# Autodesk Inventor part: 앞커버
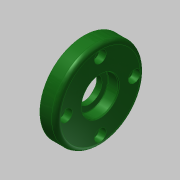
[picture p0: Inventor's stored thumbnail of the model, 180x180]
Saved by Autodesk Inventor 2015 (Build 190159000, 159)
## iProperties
Created: 2015-11
Part Number: 앞커버
Material: 알루미늄 6061
Document SubType Name: Modeling
Designer: mduedu
Density: 1 g/cm^3
Appearance: 매끄러움 - 짙은 산림 녹색
Author: mduedu
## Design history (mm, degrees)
sketch "스케치5"
  geometry: C1 r 30 at (0, 0); 2 further points
  constraints: 2 coincident, 1 centre point
  dimensions: "d66" = 60 diameter of C1
extrude "돌출2" new body sketch "스케치5" distance "d67" = 11; taper "d68" = 0 deg
sketch "스케치6"
  geometry: C1 r 16 at (0, 0); 1 further point
  constraints: 1 centre point, 1 coincident
  dimensions: "d69" = 32 diameter of C1
extrude "돌출3" join sketch "스케치6" distance "d70" = 3; taper "d71" = 0 deg
hole "구멍7" diameter "d98" = 25; stored, may be unused: countersink angle "d102" = 90 deg, drill point angle "d104" = 0 deg; dims "d96" = 10, "d97" = 10, "d99" = 6, "d100" = 4, "d101" = 2, "d103" = 3
hole "구멍8" diameter "d107" = 25; stored, may be unused: countersink angle "d111" = 90 deg, drill point angle "d113" = 0 deg; dims "d108" = 6, "d109" = 4, "d110" = 2, "d112" = 7.3, "d143" = 10, "d144" = 10
hole "구멍9" diameter "d116" = 17; stored, may be unused: countersink angle "d120" = 90 deg, drill point angle "d122" = 0 deg; dims "d114" = 10, "d115" = 10, "d117" = 6, "d118" = 4, "d119" = 2, "d121" = 7.7
chamfer "모따기2" distance "d123" = 0.7; stored, may be unused: second distance "d124" = 2, angle "d125" = 30 deg
fillet "모깎기11" dims "d126" = 0.3
fillet "모깎기13" dims "d128" = 3
fillet "모깎기14" dims "d129" = 3
fillet "모깎기15" dims "d130" = 0.3
sketch "스케치8" dims "d131" = 46
  geometry: 3 further points
  constraints: 2 vertical alignment, 1 coincident, 2 other
hole "구멍10" sketch "스케치8" at (0, 23) diameter "d132" = 4.5; stored, may be unused: countersink angle "d136" = 90 deg, drill point angle "d138" = 0 deg; dims "d133" = 6, "d134" = 8, "d135" = 4.6, "d137" = 7.7
node "솔리드2"
pattern_circular "원형 패턴4" dims angle "d140" = 360 deg
